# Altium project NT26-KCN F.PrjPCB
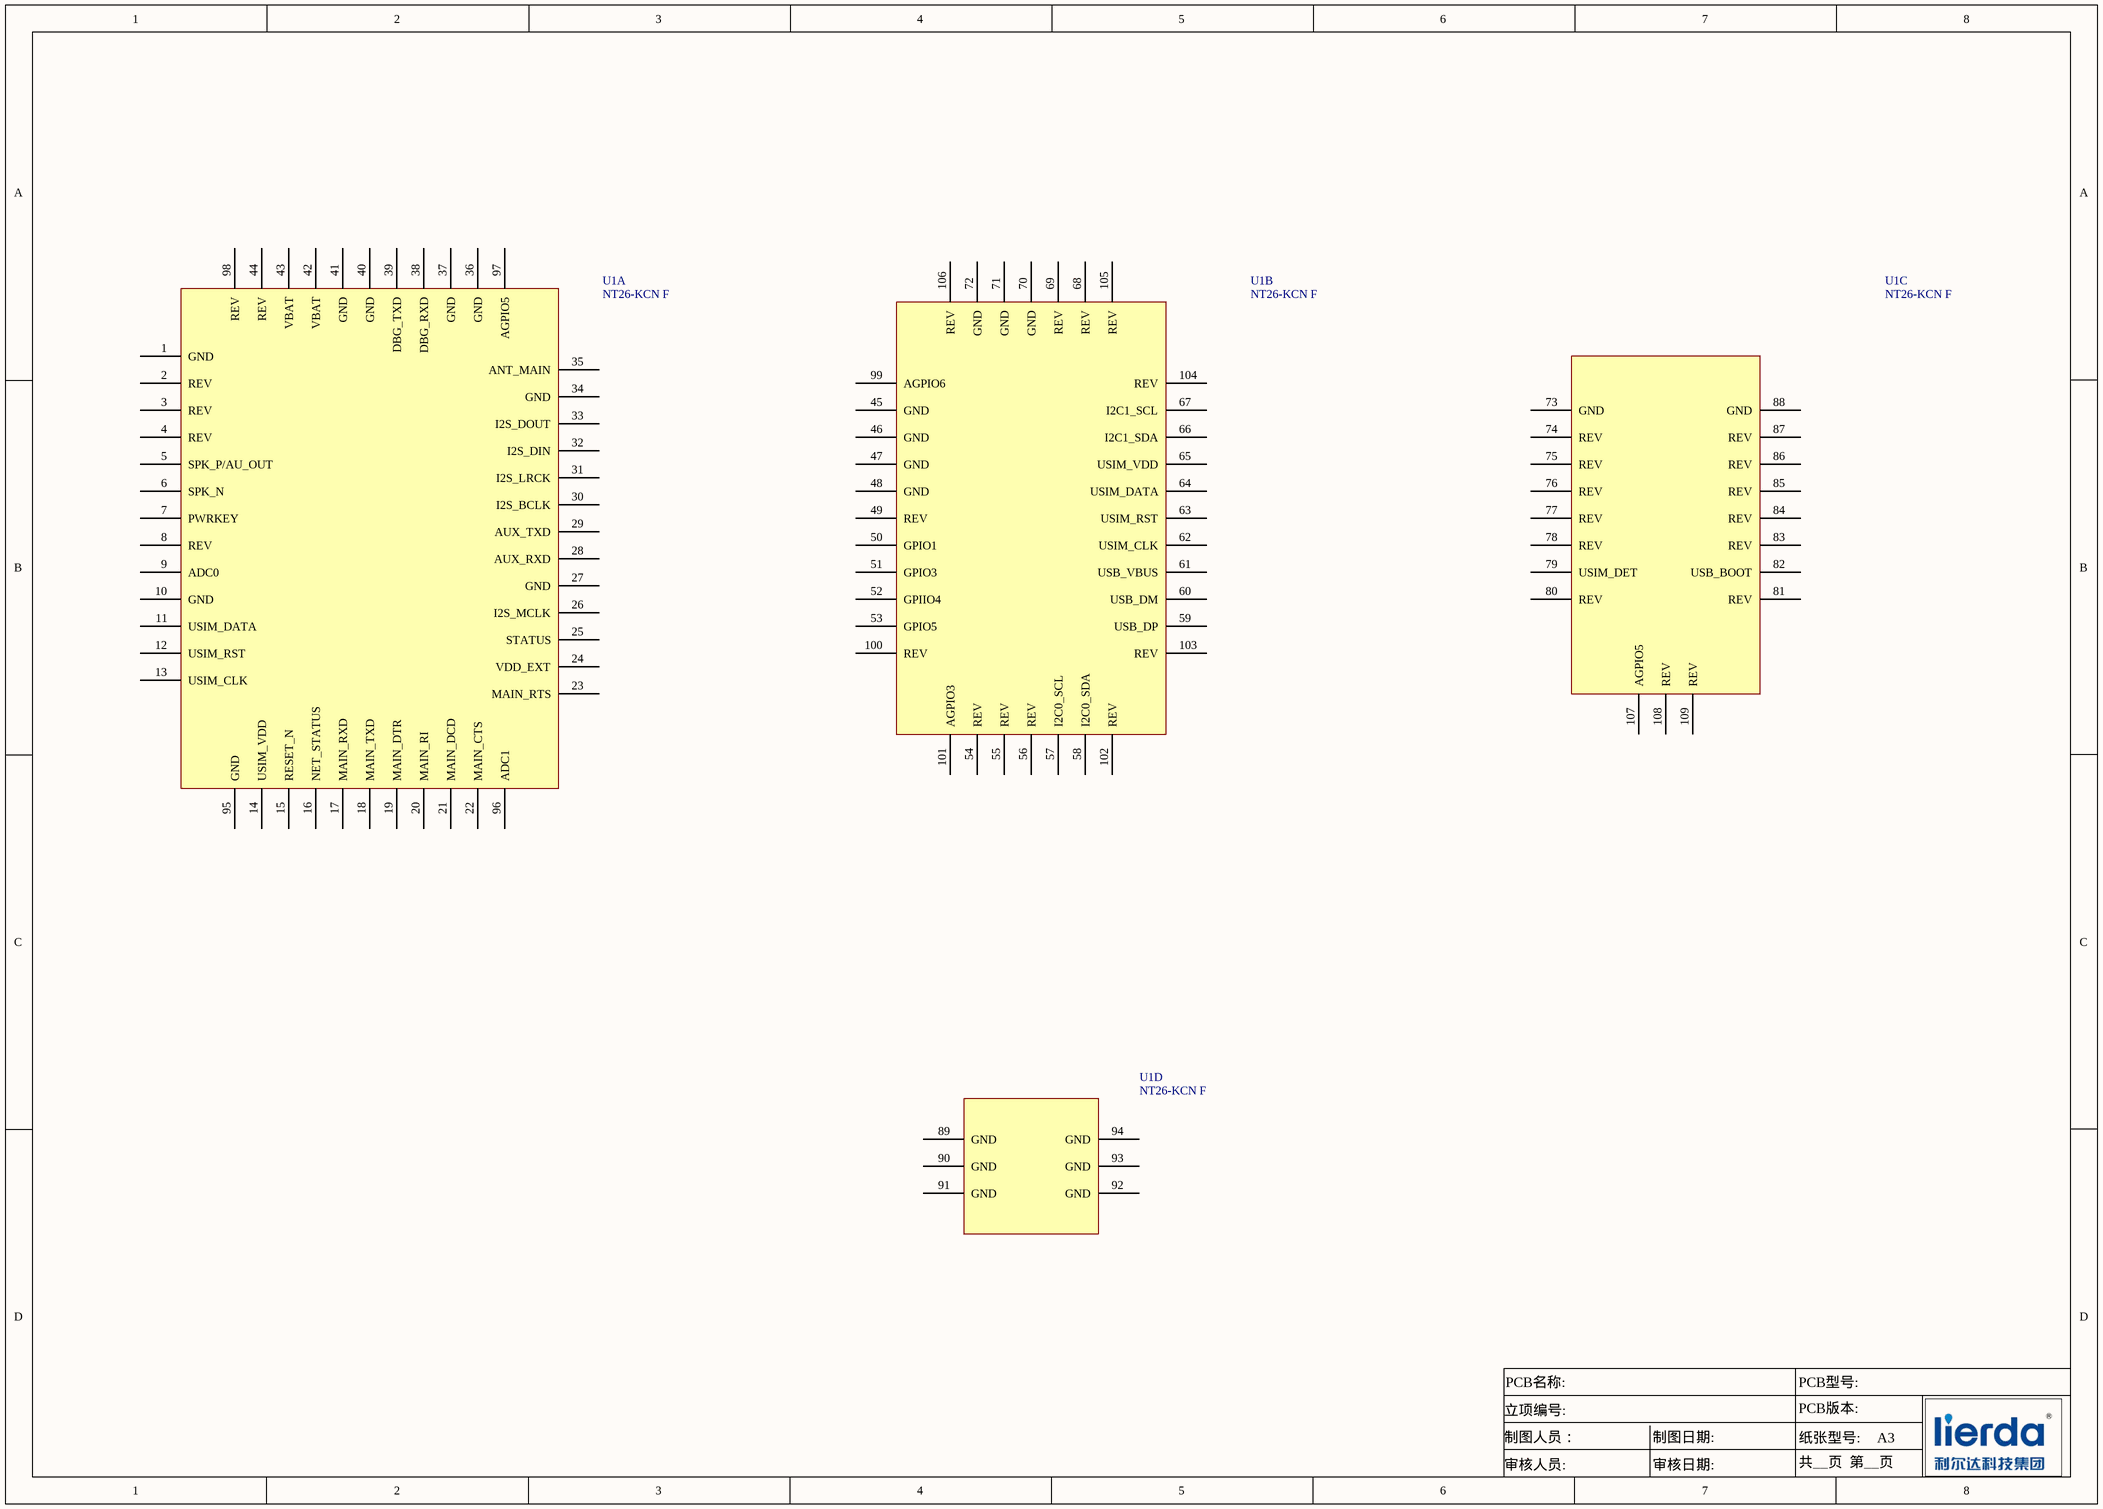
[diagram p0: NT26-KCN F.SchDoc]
1 sheet, 1 parts. Net scope: global (net labels, ports and power ports of the same name join across sheets).
Board file: NT26-KCN F.PcbDoc

## Sheet NT26-KCN F.SchDoc
size A3

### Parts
U1  NT26-KCN F  [NT26-KCN F]  (parts A,B,C,D of 4)

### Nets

Not connected (* = marked no-connect by the designer): U1 1(GND) 2(REV) 3(REV) 4(REV) 5(SPK_P/AU_OUT) 6(SPK_N) 7(PWRKEY) 8(REV) 9(ADC0) 10(GND) 11(USIM_DATA) 12(USIM_RST) 13(USIM_CLK) 14(USIM_VDD) 15(RESET_N) 16(NET_STATUS) 17(MAIN_RXD) 18(MAIN_TXD) 19(MAIN_DTR) 20(MAIN_RI) 21(MAIN_DCD) 22(MAIN_CTS) 23(MAIN_RTS) 24(VDD_EXT) 25(STATUS) 26(I2S_MCLK) 27(GND) 28(AUX_RXD) 29(AUX_TXD) 30(I2S_BCLK) 31(I2S_LRCK) 32(I2S_DIN) 33(I2S_DOUT) 34(GND) 35(ANT_MAIN) 36(GND) 37(GND) 38(DBG_RXD) 39(DBG_TXD) 40(GND) 41(GND) 42(VBAT) 43(VBAT) 44(REV) 45(GND) 46(GND) 47(GND) 48(GND) 49(REV) 50(GPIO1) 51(GPIO3) 52(GPIIO4) 53(GPIO5) 54(REV) 55(REV) 56(REV) 57(I2C0_SCL) 58(I2C0_SDA) 59(USB_DP) 60(USB_DM) 61(USB_VBUS) 62(USIM_CLK) 63(USIM_RST) 64(USIM_DATA) 65(USIM_VDD) 66(I2C1_SDA) 67(I2C1_SCL) 68(REV) 69(REV) 70(GND) 71(GND) 72(GND) 73(GND) 74(REV) 75(REV) 76(REV) 77(REV) 78(REV) 79(USIM_DET) 80(REV) 81(REV) 82(USB_BOOT) 83(REV) 84(REV) 85(REV) 86(REV) 87(REV) 88(GND) 89(GND) 90(GND) 91(GND) 92(GND) 93(GND) 94(GND) 95(GND) 96(ADC1) 97(AGPIO5) 98(REV) 99(AGPIO6) 100(REV) 101(AGPIO3) 102(REV) 103(REV) 104(REV) 105(REV) 106(REV) 107(AGPIO5) 108(REV) 109(REV)

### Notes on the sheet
- PCB名称:
- PCB型号:
- 制图人员：
- 立项编号:
- 制图日期:
- PCB版本:
- 纸张型号:
- A3
- 审核人员:
- 审核日期:
- 共__页  第__页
